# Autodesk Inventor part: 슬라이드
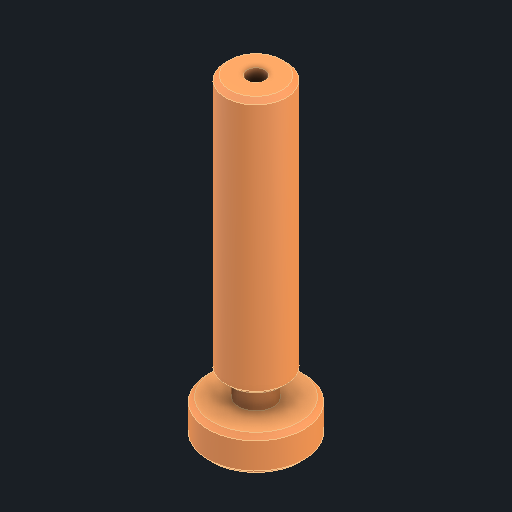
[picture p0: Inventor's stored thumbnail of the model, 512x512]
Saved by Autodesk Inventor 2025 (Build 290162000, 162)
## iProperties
Created: 2025-08
Part Number: 슬라이드
Material: 강철, 연강
Document SubType Name: Modeling
Designer: infra027
Density: 7.86 g/cm^3
Appearance: 기본값
Author: jhkim
Sending System: Autodesk Inventor 2026
Preprocessor: ST-DEVELOPER v20.1
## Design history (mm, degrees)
feature "솔리드1"
node "솔리드2"
